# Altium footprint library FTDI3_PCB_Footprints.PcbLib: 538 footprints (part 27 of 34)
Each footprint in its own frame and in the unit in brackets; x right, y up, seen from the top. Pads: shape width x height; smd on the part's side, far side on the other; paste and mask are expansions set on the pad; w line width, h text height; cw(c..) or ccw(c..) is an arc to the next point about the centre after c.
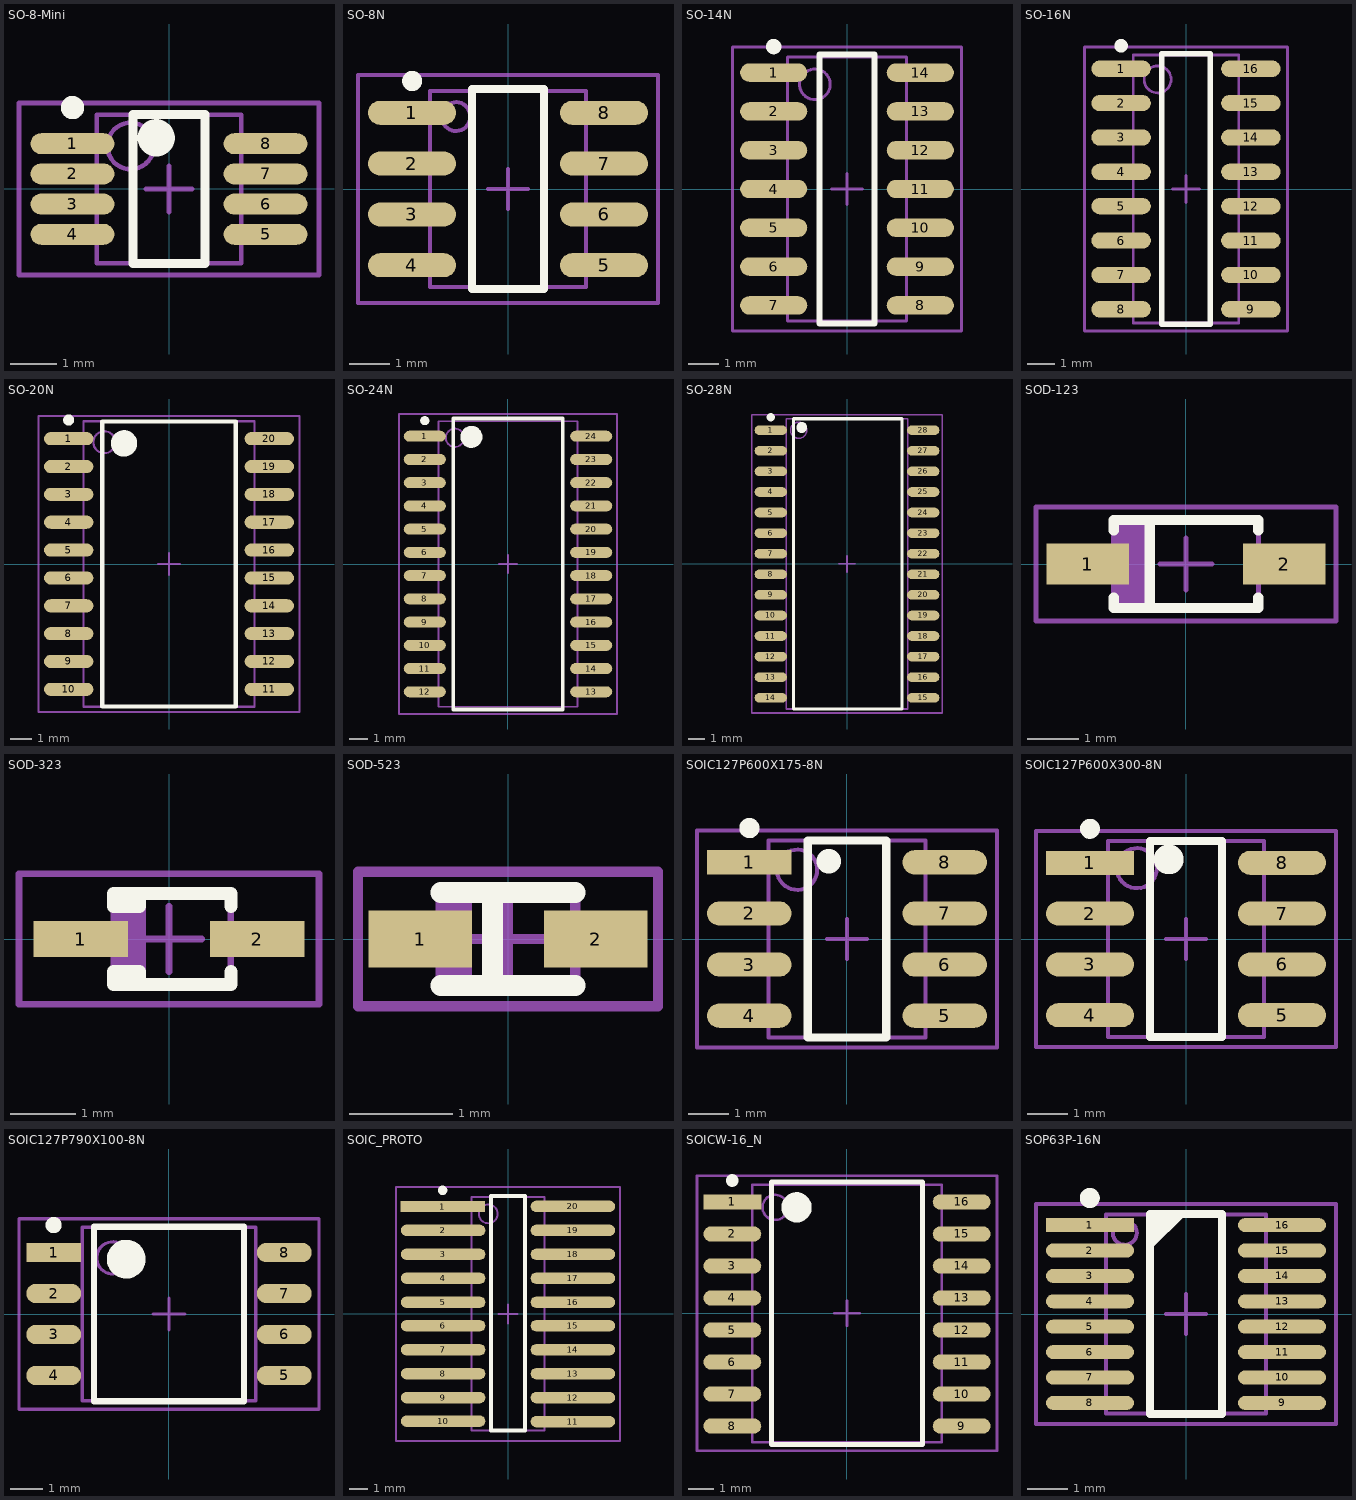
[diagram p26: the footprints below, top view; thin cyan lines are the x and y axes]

## SO-8-Mini [mm] "SO-Mini, 8-Leads, Body 3.2x3.1mm (max), Pitch 0.65mm, IPC Medium Density"
height 1.1
pads (8):
  oval 1.8x0.45 smd: 1(-2.075,0.975) 2(-2.075,0.325) 3(-2.075,-0.325) 4(-2.075,-0.975) 5(2.075,-0.975) 6(2.075,-0.325) 7(2.075,0.325) 8(2.075,0.975)
Top Overlay:
  circle w0.6: c-0.275,1.1 r0.1
  circle w0.25: c-2.075,1.75 r0.125
  lines w0.2: -0.775,-1.6 0.775,-1.6 0.775,1.6 -0.775,1.6 -0.775,-1.6
M13_Assembly_Info:
  circle w0.1: c-0.825,0.925 r0.5
  lines w0.1: -1.55,-1.6 1.55,-1.6 1.55,1.6 -1.55,1.6 -1.55,-1.6
M15_Country_Yard:
  lines w0.1: -0.5,0 0.5,0 ; 0,-0.5 0,0.5 ; -3.225,-1.85 3.225,-1.85 3.225,1.85 -3.225,1.85 -3.225,-1.85
3D body: height 1.1, standoff 0.15, extent -1.55,-1.6 1.55,1.6

## SO-8N [mm] "8-Pin Small Outline Integrated Circuit 1.27 mm Pitch, IPC Medium Density"
height 1.75
pads (8):
  oval 2.2x0.6 smd: 1(-2.4,1.905) 2(-2.4,0.635) 3(-2.4,-0.635) 4(-2.4,-1.905) 5(2.4,-1.905) 6(2.4,-0.635) 7(2.4,0.635) 8(2.4,1.905)
Top Overlay:
  circle w0.25: c-2.395,2.7 r0.125
  lines w0.2: -0.9,-2.5 -0.9,2.5 0.9,2.5 0.9,-2.5 -0.9,-2.5
M13_Assembly_Info:
  circle w0.1: c-1.3,1.81 r0.36
  lines w0.1: -1.95,-2.45 -1.95,2.45 1.95,2.45 1.95,-2.45 -1.95,-2.45
M15_Country_Yard:
  lines w0.1: -0.5,0 0.5,0 ; 0,-0.5 0,0.5 ; -3.75,-2.85 -3.75,2.85 3.75,2.85 3.75,-2.85 -3.75,-2.85
3D body: height 1.75, standoff 0, extent -1.95,-2.45 1.95,2.45

## SO-14N [mm] "14-Pin Small Outline Integrated Circuit 1.27 mm Pitch, IPC Medium Density"
height 1.75
pads (14):
  oval 2.2x0.6 smd: 1(-2.4,3.81) 2(-2.4,2.54) 3(-2.4,1.27) 4(-2.4,0) 5(-2.4,-1.27) 6(-2.4,-2.54) 7(-2.4,-3.81) 8(2.4,-3.81) 9(2.4,-2.54) 10(2.4,-1.27) 11(2.4,0) 12(2.4,1.27) 13(2.4,2.54) 14(2.4,3.81)
Top Overlay:
  circle w0.25: c-2.4,4.66 r0.125
  lines w0.2: -0.9,-4.4 0.9,-4.4 0.9,4.4 -0.9,4.4 -0.9,-4.4
M13_Assembly_Info:
  circle w0.1: c-1.05,3.425 r0.5
  lines w0.1: -1.95,-4.325 1.95,-4.325 1.95,4.325 -1.95,4.325 -1.95,-4.325
M15_Country_Yard:
  lines w0.1: -0.5,0 0.5,0 ; 0,-0.5 0,0.5 ; -3.75,-4.65 3.75,-4.65 3.75,4.65 -3.75,4.65 -3.75,-4.65
3D body: height 1.75, standoff 0, extent -1.95,-4.325 1.95,4.325

## SO-16N [mm] "16-Pin Small Outline Integrated Circuit 1.27 mm Pitch, IPC Medium Density"
height 1.75
pads (16):
  oval 2.2x0.6 smd: 1(-2.4,4.445) 2(-2.4,3.175) 3(-2.4,1.905) 4(-2.4,0.635) 5(-2.4,-0.635) 6(-2.4,-1.905) 7(-2.4,-3.175) 8(-2.4,-4.445) 9(2.4,-4.445) 10(2.4,-3.175) 11(2.4,-1.905) 12(2.4,-0.635) 13(2.4,0.635) 14(2.4,1.905) 15(2.4,3.175) 16(2.4,4.445)
Top Overlay:
  circle w0.25: c-2.4,5.295 r0.125
  lines w0.2: -0.9,-5 0.9,-5 0.9,5 -0.9,5 -0.9,-5
M13_Assembly_Info:
  circle w0.1: c-1.05,4.05 r0.5
  lines w0.1: -1.95,-4.95 1.95,-4.95 1.95,4.95 -1.95,4.95 -1.95,-4.95
M15_Country_Yard:
  lines w0.1: -0.5,0 0.5,0 ; 0,-0.5 0,0.5 ; -3.75,-5.25 3.75,-5.25 3.75,5.25 -3.75,5.25 -3.75,-5.25
3D body: height 1.75, standoff 0, extent -1.95,-4.95 1.95,4.95

## SO-20N [mm] "SOIC, 20-Leads, Body 13.0x7.8mm (max), Pitch 1.27mm, IPC Medium Density"
height 2.642
pads (20):
  oval 2.25x0.6 smd: 1(-4.575,5.715) 2(-4.575,4.445) 3(-4.575,3.175) 4(-4.575,1.905) 5(-4.575,0.635) 6(-4.575,-0.635) 7(-4.575,-1.905) 8(-4.575,-3.175) 9(-4.575,-4.445) 10(-4.575,-5.715) 11(4.575,-5.715) 12(4.575,-4.445) 13(4.575,-3.175) 14(4.575,-1.905) 15(4.575,-0.635) 16(4.575,0.635) 17(4.575,1.905) 18(4.575,3.175) 19(4.575,4.445) 20(4.575,5.715)
Top Overlay:
  circle w0.25: c-4.575,6.565 r0.125
  circle w0.6: c-2.05,5.5 r0.3
  lines w0.2: -3.05,-6.5 -3.05,6.5 3.05,6.5 3.05,-6.5 -3.05,-6.5
M13_Assembly_Info:
  circle w0.1: c-2.95,5.555 r0.5
  lines w0.1: -3.9,-6.505 -3.9,6.505 3.9,6.505 3.9,-6.505 -3.9,-6.505
M15_Country_Yard:
  lines w0.1: -0.5,0 0.5,0 ; 0,-0.5 0,0.5 ; -5.95,-6.75 -5.95,6.75 5.95,6.75 5.95,-6.75 -5.95,-6.75
3D body: height 2.64, standoff 0.31, extent -3.9,-6.505 3.9,6.505

## SO-24N [mm] "SOIC, 24-Leads, Body 15.4x7.5mm, Pitch 1.27mm, IPC Medium Density"
height 2.65
pads (24):
  oval 2.3x0.6 smd: 1(-4.55,6.985) 2(-4.55,5.715) 3(-4.55,4.445) 4(-4.55,3.175) 5(-4.55,1.905) 6(-4.55,0.635) 7(-4.55,-0.635) 8(-4.55,-1.905) 9(-4.55,-3.175) 10(-4.55,-4.445) 11(-4.55,-5.715) 12(-4.55,-6.985) 13(4.55,-6.985) 14(4.55,-5.715) 15(4.55,-4.445) 16(4.55,-3.175) 17(4.55,-1.905) 18(4.55,-0.635) 19(4.55,0.635) 20(4.55,1.905) 21(4.55,3.175) 22(4.55,4.445) 23(4.55,5.715) 24(4.55,6.985)
Top Overlay:
  circle w0.6: c-2,6.95 r0.3
  circle w0.25: c-4.55,7.835 r0.125
  lines w0.2: -3,-7.95 3,-7.95 3,7.95 -3,7.95 -3,-7.95
M13_Assembly_Info:
  circle w0.1: c-2.9,6.9 r0.5
  lines w0.1: -3.8,-7.8 3.8,-7.8 3.8,7.8 -3.8,7.8 -3.8,-7.8
M15_Country_Yard:
  lines w0.1: -0.5,0 0.5,0 ; 0,-0.5 0,0.5 ; -5.95,-8.2 5.95,-8.2 5.95,8.2 -5.95,8.2 -5.95,-8.2
3D body: height 2.65, standoff 0, extent -3.8,-7.8 3.8,7.8

## SO-28N [mm] "SOIC, 28-Leads, Body 17.9x7.5mm (max), Pitch 1.27mm, IPC Medium Density"
height 2.65
pads (28):
  oval 2x0.6 smd: 1(-4.7,8.25) 2(-4.7,6.98) 3(-4.7,5.71) 4(-4.7,4.44) 5(-4.7,3.17) 6(-4.7,1.9) 7(-4.7,0.63) 8(-4.7,-0.64) 9(-4.7,-1.91) 10(-4.7,-3.18) 11(-4.7,-4.45) 12(-4.7,-5.72) 13(-4.7,-6.99) 14(-4.7,-8.26) 15(4.7,-8.26) 16(4.7,-6.99) 17(4.7,-5.72) 18(4.7,-4.45) 19(4.7,-3.18) 20(4.7,-1.91) 21(4.7,-0.64) 22(4.7,0.63) 23(4.7,1.9) 24(4.7,3.17) 25(4.7,4.44) 26(4.7,5.71) 27(4.7,6.98) 28(4.7,8.25)
Top Overlay:
  circle w0.6: c-2.795,8.42 r0.035
  circle w0.25: c-4.705,9.05 r0.125
  lines w0.2: -3.3,-8.95 3.4,-8.95 3.4,8.95 -3.3,8.95 -3.3,-8.95
M13_Assembly_Info:
  circle w0.1: c-2.98,8.25 r0.5
  lines w0.1: -3.75,-8.95 3.75,-8.95 3.75,8.95 -3.75,8.95 -3.75,-8.95
M15_Country_Yard:
  lines w0.1: -0.5,0 0.5,0 ; 0,-0.5 0,0.5 ; -5.875,-9.2 5.875,-9.2 5.875,9.2 -5.875,9.2 -5.875,-9.2
3D body: height 2.65, standoff 0.3, extent -3.75,-8.95 3.75,8.95

## SOD-123 [mm] "SOD-123; 2 Leads; Body 2.8 x 1.7 mm, (LxW)"
height 1.35
pads (2):
  rect 1.6x0.8 smd: 1(-1.9,0) 2(1.9,0)
Top Overlay:
  lines w0.2: -1.4,-0.65 -1.4,-0.85 1.4,-0.85 1.4,-0.65 ; -1.4,0.65 -1.4,0.85 1.4,0.85 1.4,0.65 ; -0.7,-0.85 -0.7,0.85
M13_Assembly_Info:
  rectangle: -1.4,-0.85 -0.775,0.85
  lines w0.1: -1.4,-0.85 -1.4,0.85 1.4,0.85 1.4,-0.85 -1.4,-0.85
M15_Country_Yard:
  lines w0.1: -0.5,0 0.5,0 ; 0,-0.5 0,0.5 ; -2.9,-1.1 2.9,-1.1 2.9,1.1 -2.9,1.1 -2.9,-1.1
3D body: height 0, standoff 0, extent -1.4,-0.85 1.4,0.85

## SOD-323 [mm] "SOD-323/SC-76; 2 Leads; Body 1.8 x 1.4 mm, (LxW)"
height 1.1
pads (2):
  rect 1.45x0.55 smd: 1(-1.35,0) 2(1.35,0)
Top Overlay:
  lines w0.2: -0.45,-0.7 -0.45,-0.5 -0.85,-0.5 -0.85,-0.7 0.95,-0.7 0.95,-0.5 ; -0.45,0.7 -0.45,0.5 -0.85,0.5 -0.85,0.7 0.95,0.7 0.95,0.5
M13_Assembly_Info:
  rectangle: -0.85,-0.7 -0.35,0.7
  lines w0.1: -0.85,-0.7 0.95,-0.7 0.95,0.7 -0.85,0.7 -0.85,-0.7
M15_Country_Yard:
  lines w0.1: -0.5,0 0.5,0 ; 0,-0.5 0,0.5 ; -2.3,-1 2.3,-1 2.3,1 -2.3,1 -2.3,-1
3D body: height 0, standoff 0, extent -0.85,-0.7 0.95,0.7

## SOD-523 [mm] "SOD-523; 2 Leads; Body 1.3 x 0.35 mm, (LxW)"
height 0.65
pads (2):
  rect 1x0.55 smd: 1(-0.85,0) 2(0.85,0)
Top Overlay:
  lines w0.2: -0.65,-0.45 0.65,-0.45 ; -0.65,0.45 0.65,0.45 ; -0.15,-0.45 -0.15,0.45
M13_Assembly_Info:
  rectangle: -0.65,-0.45 -0.35,0.45
  lines w0.1: -0.65,-0.45 0.65,-0.45 0.65,0.45 -0.65,0.45 -0.65,-0.45
M15_Country_Yard:
  lines w0.1: -0.5,0 0.5,0 ; 0,-0.5 0,0.5 ; -1.45,-0.65 -1.45,0.65 1.45,0.65 1.45,-0.65 -1.45,-0.65
3D body: height 0, standoff 0, extent -0.65,-0.45 0.65,0.45

## SOIC127P600X175-8N [mm] "SOIC, 8-Leads, Body 4.9x3.9mm (max), Pitch 1.27mm, IPC Medium Density"
height 1.75
pads (8):
  rect 2.1x0.6 smd: 1(-2.425,1.905)
  oval 2.1x0.6 smd: 2(-2.425,0.635) 3(-2.425,-0.635) 4(-2.425,-1.905) 5(2.425,-1.905) 6(2.425,-0.635) 7(2.425,0.635) 8(2.425,1.905)
Top Overlay:
  circle w0.6: c-0.455,1.93 r0.005
  circle w0.25: c-2.425,2.755 r0.125
  lines w0.2: -0.975,-2.45 0.975,-2.45 0.975,2.45 -0.975,2.45 -0.975,-2.45
M13_Assembly_Info:
  circle w0.1: c-1.24,1.72 r0.5
  lines w0.1: -1.95,-2.45 1.95,-2.45 1.95,2.45 -1.95,2.45 -1.95,-2.45
M15_Country_Yard:
  lines w0.1: -0.5,0 0.5,0 ; 0,-0.5 0,0.5 ; -3.725,-2.7 3.725,-2.7 3.725,2.7 -3.725,2.7 -3.725,-2.7
3D body: height 1.75, standoff 0.25, extent -1.95,-2.45 1.95,2.45

## SOIC127P600X300-8N [mm] "SOIC, 8-Leads, Body 4.9x3.9mm (max), Pitch 1.27mm, IPC Medium Density"
height 3
pads (8):
  rect 2.2x0.6 smd: 1(-2.4,1.905)
  oval 2.2x0.6 smd: 2(-2.4,0.635) 3(-2.4,-0.635) 4(-2.4,-1.905) 5(2.4,-1.905) 6(2.4,-0.635) 7(2.4,0.635) 8(2.4,1.905)
Top Overlay:
  circle w0.25: c-2.4,2.755 r0.125
  circle w0.6: c-0.431,1.99 r0.071
  lines w0.2: -0.9,-2.45 -0.9,2.45 0.9,2.45 0.9,-2.45 -0.9,-2.45
M13_Assembly_Info:
  circle w0.1: c-1.23,1.77 r0.5
  lines w0.1: -1.95,-2.45 -1.95,2.45 1.95,2.45 1.95,-2.45 -1.95,-2.45
M15_Country_Yard:
  lines w0.1: -0.5,0 0.5,0 ; 0,-0.5 0,0.5 ; -3.75,-2.7 -3.75,2.7 3.75,2.7 3.75,-2.7 -3.75,-2.7
3D body: height 3, standoff 0.2, extent -1.95,-2.45 1.95,2.45

## SOIC127P790X100-8N [mm] "SOIC, 8-Leads, Body 5.4x5.4mm (max), Pitch 1.27mm, IPC Medium Density"
height 1
pads (8):
  rect 1.7x0.6 smd: 1(-3.575,1.905)
  oval 1.7x0.6 smd: 2(-3.575,0.635) 3(-3.575,-0.635) 4(-3.575,-1.905) 5(3.575,-1.905) 6(3.575,-0.635) 7(3.575,0.635) 8(3.575,1.905)
Top Overlay:
  circle w0.6: c-1.325,1.7 r0.3
  circle w0.25: c-3.575,2.755 r0.125
  lines w0.2: -2.325,-2.7 2.325,-2.7 2.325,2.7 -2.325,2.7 -2.325,-2.7
M13_Assembly_Info:
  circle w0.1: c-1.74,1.74 r0.5
  lines w0.1: -2.69,-2.69 2.69,-2.69 2.69,2.69 -2.69,2.69 -2.69,-2.69
M15_Country_Yard:
  lines w0.1: -0.5,0 0.5,0 ; 0,-0.5 0,0.5 ; -4.65,-2.95 4.65,-2.95 4.65,2.95 -4.65,2.95 -4.65,-2.95
3D body: height 1, standoff 0.15, extent -2.69,-2.69 2.69,2.69

## SOIC_PROTO [mm]
pads (20):
  rect 4.5x0.6 smd: 1(-3.475,5.715)
  oval 4.5x0.6 smd: 2(-3.45,4.45) 3(-3.45,3.175) 4(-3.45,1.9) 5(-3.45,0.625) 6(-3.45,-0.625) 7(-3.45,-1.9) 8(-3.45,-3.175) 9(-3.45,-4.45) 10(-3.45,-5.7) 11(3.45,-5.726) 12(3.45,-4.45) 13(3.45,-3.175) 14(3.45,-1.9) 15(3.45,-0.625) 16(3.45,0.625) 17(3.45,1.9) 18(3.45,3.175) 19(3.45,4.45) 20(3.45,5.725)
Top Overlay:
  circle w0.25: c-3.475,6.575 r0.125
  lines w0.2: -0.9,-6.2 0.9,-6.2 0.9,6.275 -0.9,6.275 -0.9,-6.2
M13_Assembly_Info:
  circle w0.1: c-1.05,5.325 r0.5
  lines w0.1: -1.95,-6.2 1.95,-6.2 1.95,6.225 -1.95,6.225 -1.95,-6.2
M15_Country_Yard:
  lines w0.1: -0.5,0 0.5,0 ; 0,-0.5 0,0.5 ; -5.95,-6.75 5.95,-6.75 5.95,6.75 -5.95,6.75 -5.95,-6.75
3D body: height 1.75, standoff 0, extent -1.95,-6.2 1.95,6.225

## SOICW-16_N [mm] "SOIC-Wide, 16-Leads, Body 12.8x7.5mm, Pitch 1.27mm, IPC Medium Density"
height 2.65
pads (16):
  rect 2.3x0.6 smd: 1(-4.55,4.42)
  oval 2.3x0.6 smd: 2(-4.55,3.15) 3(-4.55,1.88) 4(-4.55,0.61) 5(-4.55,-0.66) 6(-4.55,-1.93) 7(-4.55,-3.2) 8(-4.55,-4.47) 9(4.55,-4.47) 10(4.55,-3.2) 11(4.55,-1.93) 12(4.55,-0.66) 13(4.55,0.61) 14(4.55,1.88) 15(4.55,3.15) 16(4.55,4.42)
Top Overlay:
  circle w0.6: c-2,4.205 r0.3
  circle w0.25: c-4.55,5.27 r0.125
  lines w0.2: -3,-5.195 3,-5.195 3,5.205 -3,5.205 -3,-5.195
M13_Assembly_Info:
  circle w0.1: c-2.85,4.205 r0.5
  lines w0.1: -3.75,-5.105 3.75,-5.105 3.75,5.105 -3.75,5.105 -3.75,-5.105
M15_Country_Yard:
  lines w0.1: -0.5,0 0.5,0 ; 0,-0.5 0,0.5 ; -5.95,-5.445 5.95,-5.445 5.95,5.455 -5.95,5.455 -5.95,-5.445
3D body: height 2.65, standoff 0, extent -3.75,-5.105 3.75,5.105

## SOP63P-16N [mm] "SOP, 16-Leads, Body 5.0x4.0mm (max), Pitch 0.63mm, IPC Medium Density"
height 1.727
pads (16):
  rect 2.2x0.35 smd: 1(-2.4,2.222)
  oval 2.2x0.35 smd: 2(-2.4,1.587) 3(-2.4,0.953) 4(-2.4,0.318) 5(-2.4,-0.318) 6(-2.4,-0.953) 7(-2.4,-1.587) 8(-2.4,-2.222) 9(2.4,-2.222) 10(2.4,-1.587) 11(2.4,-0.953) 12(2.4,-0.318) 13(2.4,0.318) 14(2.4,0.953) 15(2.4,1.587) 16(2.4,2.222)
Top Overlay:
  circle w0.25: c-2.405,2.9 r0.125
  region: -0.9,2.5 0,2.5 -0.9,1.6
  lines w0.2: -0.9,-2.5 0.9,-2.5 0.9,2.5 -0.9,2.5 -0.9,-2.5
M13_Assembly_Info:
  circle w0.1: c-1.53,2.03 r0.3
  lines w0.1: -1.995,-2.49 1.995,-2.49 1.995,2.49 -1.995,2.49 -1.995,-2.49
M15_Country_Yard:
  lines w0.1: -0.5,0 0.5,0 ; 0,-0.5 0,0.5 ; -3.75,-2.75 3.75,-2.75 3.75,2.75 -3.75,2.75 -3.75,-2.75
3D body: height 1.73, standoff 0.25, extent -1.995,-2.49 1.995,2.49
